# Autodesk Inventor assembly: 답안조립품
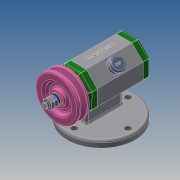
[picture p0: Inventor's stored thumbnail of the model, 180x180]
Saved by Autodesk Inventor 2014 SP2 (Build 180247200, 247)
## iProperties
Created: 2021-02
Part Number: 답안조립품
Document SubType Name: Assembly
Designer: kb542-10
Author: kb542-10
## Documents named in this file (14)
- C:\Users\kb542-10\Desktop\710204V1027\답안조립품.iam
- C:\Users\kb542-10\Desktop\710204V1027\V벨트풀리.ipt
- C:\Users\kb542-10\Desktop\710204V1027\고무캡.ipt
- C:\Users\kb542-10\Desktop\710204V1027\너트 M8.ipt
- C:\Users\kb542-10\Desktop\710204V1027\뒤커버.ipt
- C:\Users\kb542-10\Desktop\710204V1027\베어링 15 x 32 x 9.ipt
- C:\Users\kb542-10\Desktop\710204V1027\본체.ipt
- C:\Users\kb542-10\Desktop\710204V1027\볼트 M4 x 12.ipt
- C:\Users\kb542-10\Desktop\710204V1027\스프링와셔 8.ipt
- C:\Users\kb542-10\Desktop\710204V1027\앞커버.ipt
- C:\Users\kb542-10\Desktop\710204V1027\오일 실 15 25 7.ipt
- C:\Users\kb542-10\Desktop\710204V1027\와셔 8x17.ipt
- C:\Users\kb542-10\Desktop\710204V1027\축.ipt
- C:\Users\kb542-10\Desktop\710204V1027\키 3 x 3 x 12.ipt
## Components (2 placed, 2 different names)
1. V벨트풀리:1
2. 고무캡:1
